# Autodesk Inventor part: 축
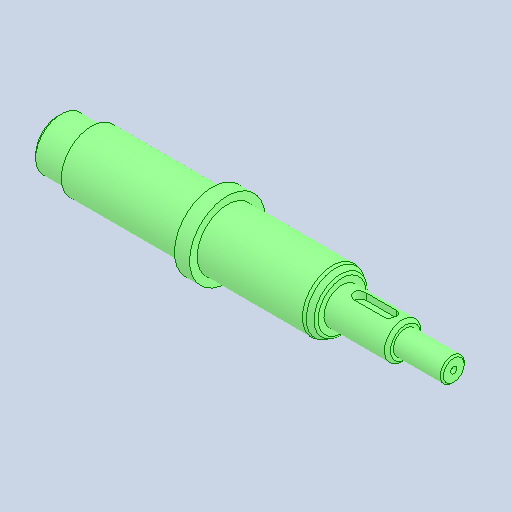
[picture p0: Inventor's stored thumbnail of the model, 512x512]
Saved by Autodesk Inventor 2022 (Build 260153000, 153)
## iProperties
Created: 2024-11
Part Number: 축
Material: 강철, 탄소
Document SubType Name: Modeling
Designer: PC-12
Density: 7.85 g/cm^3
Appearance: 기본값
Author: jhkim
Sending System: Autodesk Inventor 2025
Preprocessor: ST-DEVELOPER v20
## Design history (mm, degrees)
node "축1"
node "솔리드2"
node "솔리드1"
